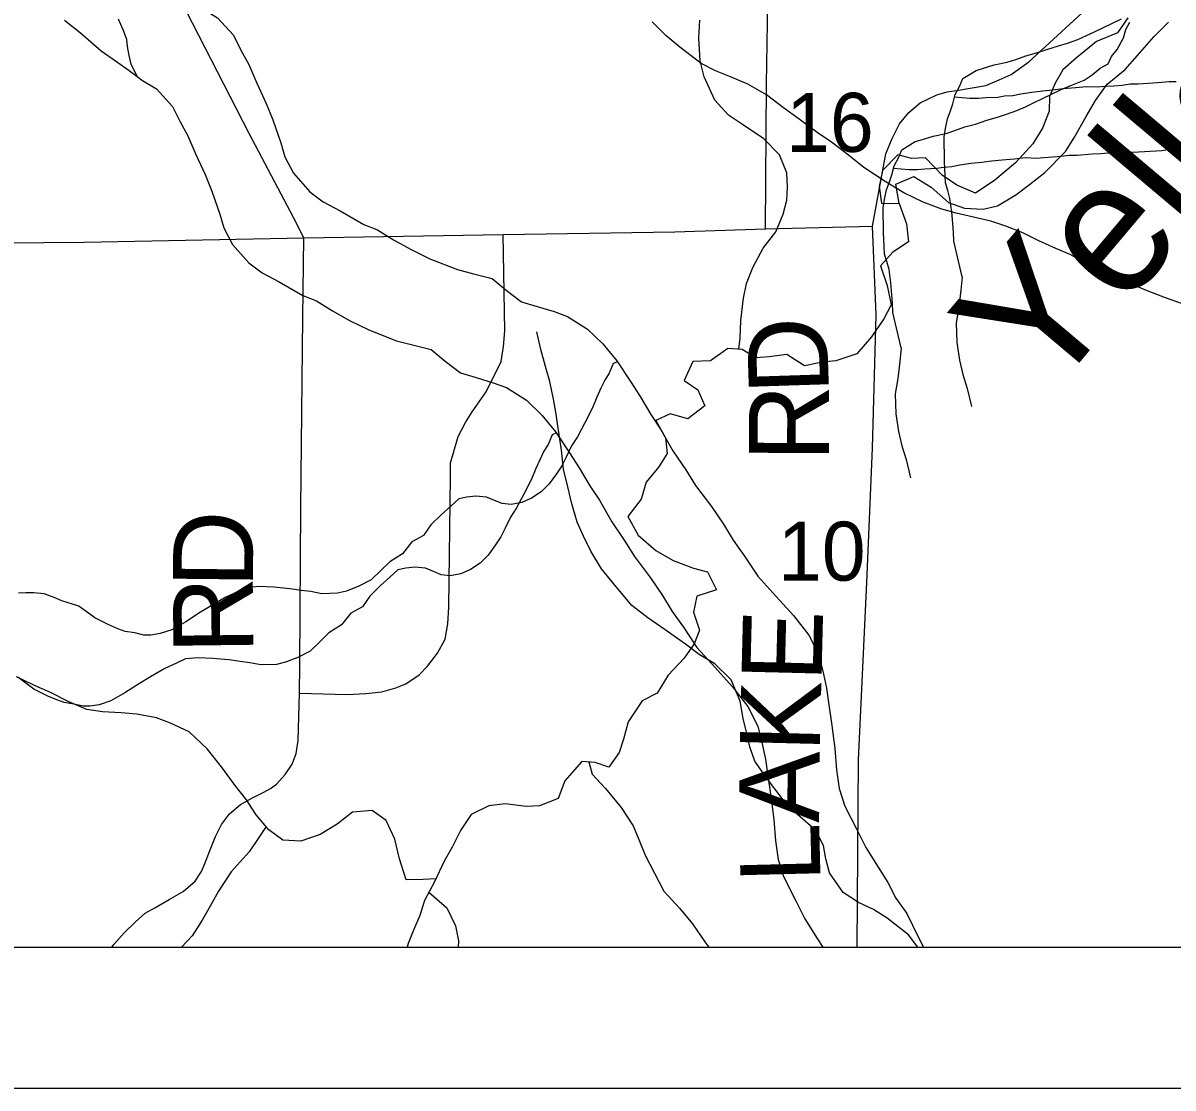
# Model space of a CAD drawing. Extents: x -21.1 to 50.3, y 0 to 22.1.
# Drawn here: x 7.468 to 8.284, y 14 to 14.756 of the extents above; entities that cross this region are included whole.
import ezdxf

# ---------------------------------------------------------------- set-up
doc = ezdxf.new("R2010")
doc.units = 0
for name, color, linetype in [('GM_X_County', 7, 'Continuous'), ('GM_X_County_Road', 7, 'Continuous'), ('GM_X_County_Road_Text', 7, 'Continuous'), ('GM_X_Major_River', 7, 'Continuous'), ('GM_X_Minor_Lake', 7, 'Continuous'), ('GM_X_Minor_River', 7, 'Continuous'), ('GM_X_Minor_River_Text', 7, 'Continuous'), ('GM_X_Section_Text', 7, 'Continuous'), ('GM_X_State_Route', 7, 'Continuous'), ('GM_X_Township_Road', 7, 'Continuous'), ('SH_Cut_Line', 7, 'Continuous'), ('SH_Data', 7, 'Continuous')]:
    doc.layers.add(name, color=color, linetype=linetype)

msp = doc.modelspace()

# ---------------------------------------------------------------- linework, layer by layer
at = {"layer": 'GM_X_County'}
msp.add_lwpolyline([(8.9, 14.74638), (8.9, 20.9), (2.1, 20.9), (2.1, 14.1), (8.89319, 14.1)], dxfattribs=at)
at = {"layer": 'GM_X_County_Road'}
for points in [[(7.6645, 14.30049), (7.66528, 14.41199), (7.66666, 14.54699), (7.66735, 14.60343), (7.66021, 14.61749), (7.62842, 14.67761), (7.57474, 14.78243), (7.56737, 14.79649), (7.56276, 14.80962), (7.56092, 14.82021), (7.56023, 14.83219), (7.56046, 14.84394), (7.56138, 14.90107), (7.56345, 15.14435), (7.56542, 15.20657), (7.56542, 15.2311), (7.5677, 15.5301)], [(8.07096, 14.61173), (8.08041, 14.6631), (8.08502, 14.67393), (8.09009, 14.68452), (8.09677, 14.69259), (8.10483, 14.69927), (8.11658, 14.70503), (8.12395, 14.7071), (8.13063, 14.70802), (8.15136, 14.71171), (8.16104, 14.71563), (8.16933, 14.71954), (8.182, 14.72853), (8.22854, 14.77138)], [(7.66735, 14.60343), (7.8088, 14.60597), (7.93063, 14.60771), (7.9951, 14.60992), (8.07096, 14.61173)], [(8.06009, 14.1), (8.06117, 14.23291), (8.06709, 14.3589), (8.07112, 14.4541), (8.07372, 14.54882), (8.07096, 14.61173)], [(7.22504, 14.59814), (7.51139, 14.60044), (7.66735, 14.60343)], [(7.59993, 14.16665), (7.60469, 14.17863), (7.60884, 14.18715), (7.6146, 14.19452), (7.62243, 14.2012), (7.63049, 14.20581), (7.63902, 14.20996), (7.64362, 14.21272), (7.648, 14.21572), (7.65399, 14.22263), (7.65906, 14.23), (7.66182, 14.23737), (7.66321, 14.24659), (7.66436, 14.28022), (7.6645, 14.30049)], [(7.53115, 14.1), (7.53258, 14.10191), (7.53973, 14.11021), (7.54779, 14.11804), (7.5547, 14.12403), (7.56161, 14.12795), (7.57175, 14.1337), (7.58165, 14.13946), (7.59018, 14.14684), (7.59478, 14.15375), (7.59663, 14.15812), (7.59847, 14.16296), (7.59993, 14.16665)]]:
    msp.add_lwpolyline(points, dxfattribs=at)
at = {"layer": 'GM_X_Major_River'}
for points in [[(7.59609, 14.76577), (7.60601, 14.75977), (7.61749, 14.74734), (7.62251, 14.73676), (7.62828, 14.72655), (7.63408, 14.71332), (7.64064, 14.69895), (7.64529, 14.68723), (7.65111, 14.67095), (7.65384, 14.66111), (7.66001, 14.6494), (7.67149, 14.63621), (7.68104, 14.62907), (7.69323, 14.62272), (7.71, 14.61298), (7.71952, 14.60927), (7.73096, 14.60215), (7.74315, 14.59541), (7.75687, 14.58869), (7.77638, 14.581)], [(7.49744, 14.75807), (7.5089, 14.74905), (7.52342, 14.73627), (7.53372, 14.72914), (7.54326, 14.72238), (7.5528, 14.71525)], [(7.5528, 14.71525), (7.56272, 14.70926), (7.5742, 14.69682), (7.57922, 14.68624), (7.58499, 14.67604), (7.59079, 14.6628), (7.59735, 14.64844), (7.602, 14.63671), (7.60782, 14.62044), (7.61055, 14.6106), (7.61672, 14.59888), (7.6282, 14.58569), (7.63775, 14.57856), (7.64994, 14.5722), (7.66671, 14.56247), (7.67623, 14.55875), (7.68767, 14.55163), (7.69987, 14.5449), (7.71358, 14.53818), (7.73309, 14.53048)], [(7.77638, 14.581), (7.78775, 14.57804), (7.80101, 14.57472), (7.8109, 14.56644), (7.82193, 14.55817), (7.83293, 14.55483), (7.84506, 14.55112), (7.85454, 14.54777), (7.8686, 14.53877), (7.87964, 14.52822), (7.88956, 14.51615), (7.89911, 14.50143), (7.90599, 14.49085), (7.91365, 14.47801), (7.92052, 14.46781), (7.92933, 14.45232), (7.9385, 14.43873), (7.94538, 14.42778), (7.95683, 14.41269), (7.96524, 14.40023), (7.97212, 14.3889), (7.98014, 14.37757), (7.9897, 14.36323), (8.00037, 14.35154), (8.01485, 14.33533), (8.02592, 14.32137), (8.03282, 14.30739), (8.03631, 14.29376), (8.03827, 14.28391), (8.03985, 14.27368), (8.04223, 14.25739), (8.04423, 14.24109), (8.04546, 14.22593), (8.04744, 14.21267), (8.05131, 14.20018), (8.05974, 14.18393), (8.06626, 14.1707), (8.07505, 14.15672), (8.08193, 14.14577), (8.08768, 14.13481), (8.09532, 14.12386), (8.10338, 14.10723), (8.10724, 14.1)], [(7.73309, 14.53048), (7.74446, 14.52753), (7.75773, 14.5242), (7.76762, 14.51592), (7.77864, 14.50765), (7.78964, 14.50432), (7.80177, 14.50061), (7.81125, 14.49726), (7.82531, 14.48825), (7.83635, 14.47771), (7.84627, 14.46564), (7.85583, 14.45091), (7.8627, 14.44034), (7.87036, 14.42749), (7.87724, 14.4173), (7.88604, 14.40181), (7.89521, 14.38822), (7.90209, 14.37726), (7.91354, 14.36217), (7.92195, 14.34971), (7.92883, 14.33838), (7.93685, 14.32706), (7.94641, 14.31271), (7.95708, 14.30102), (7.97156, 14.28482), (7.98263, 14.27086), (7.98953, 14.25687), (7.99302, 14.24324), (7.99498, 14.23339), (7.99656, 14.22316), (7.99894, 14.20687), (8.00094, 14.19057), (8.00217, 14.17541), (8.00415, 14.16215), (8.00802, 14.14966), (8.01645, 14.13341), (8.02297, 14.12018), (8.03176, 14.10621), (8.03566, 14.1)]]:
    msp.add_lwpolyline(points, dxfattribs=at)
at = {"layer": 'GM_X_Minor_Lake'}
for points in [[(8.25235, 14.75979), (8.24486, 14.74908), (8.23012, 14.74286), (8.2158, 14.73133), (8.20601, 14.72288), (8.20078, 14.71333), (8.1967, 14.70379), (8.19641, 14.69353), (8.19158, 14.68133), (8.18485, 14.67025), (8.17245, 14.65683), (8.15776, 14.64453), (8.14418, 14.63529), (8.13085, 14.64086), (8.12054, 14.64799), (8.10867, 14.66041), (8.09881, 14.65994), (8.08892, 14.66251), (8.07801, 14.65139), (8.07584, 14.63997), (8.07746, 14.6282)], [(8.08999, 14.62794), (8.08759, 14.6416), (8.10044, 14.64703), (8.11265, 14.63955), (8.12489, 14.62865), (8.13631, 14.62457), (8.1496, 14.62394), (8.15982, 14.62632), (8.17266, 14.63403), (8.18246, 14.64135), (8.19339, 14.64981), (8.20805, 14.66476), (8.21441, 14.67508), (8.22263, 14.6896), (8.22935, 14.70106), (8.2376, 14.71254), (8.25041, 14.72292), (8.25905, 14.73288), (8.27069, 14.74628), (8.28122, 14.75664)], [(8.07746, 14.6282), (8.08999, 14.62794)]]:
    msp.add_lwpolyline(points, dxfattribs=at)
at = {"layer": 'GM_X_Minor_River'}
for points in [[(7.54914, 14.71799), (7.54484, 14.72691), (7.54328, 14.73298), (7.5421, 14.73943), (7.54169, 14.74437), (7.53899, 14.75119), (7.5359, 14.75877)], [(8.295, 14.55524), (8.2791, 14.56103), (8.26661, 14.56566), (8.25526, 14.57028), (8.24428, 14.57414), (8.23369, 14.57952), (8.22197, 14.58566), (8.21138, 14.5918), (8.20116, 14.59603), (8.18906, 14.60142), (8.17771, 14.60718), (8.1656, 14.61181), (8.155, 14.61529), (8.13037, 14.62113), (8.12015, 14.62385), (8.1069, 14.62886), (8.09328, 14.6354), (8.08005, 14.64344), (8.06494, 14.6534), (8.05399, 14.6622), (8.04191, 14.67137), (8.03171, 14.67827), (8.01887, 14.68783), (8.00792, 14.69587), (7.99584, 14.70505), (7.98261, 14.71272), (7.97012, 14.71772), (7.95952, 14.72196), (7.94931, 14.72734), (7.93421, 14.73881), (7.9244, 14.74722), (7.91459, 14.75676)], [(7.97607, 14.52447), (7.977, 14.53227), (7.97765, 14.54481), (7.9794, 14.56079), (7.98159, 14.57107), (7.98604, 14.58251), (7.9935, 14.59626), (8.00251, 14.60774), (8.00771, 14.62033), (8.01028, 14.63023), (8.01057, 14.63973), (8.0101, 14.64961), (8.00505, 14.66248), (7.99395, 14.67377), (7.97944, 14.68352), (7.96875, 14.69064), (7.95917, 14.70118), (7.95143, 14.71783), (7.94867, 14.7292), (7.94777, 14.74515), (7.94841, 14.75808)], [(8.09144, 14.52534), (8.08556, 14.5506), (8.08514, 14.55705), (8.08473, 14.56313), (8.08392, 14.57148), (8.08273, 14.58097), (8.08117, 14.58666), (8.07962, 14.59197), (8.07921, 14.59729), (8.07877, 14.60716), (8.07867, 14.62501), (8.07978, 14.63186), (8.08089, 14.63756), (8.08314, 14.64327), (8.08463, 14.64822), (8.0865, 14.65469), (8.08952, 14.6604), (8.09177, 14.66611), (8.10125, 14.67186), (8.10657, 14.67341), (8.11417, 14.67573), (8.1233, 14.67768), (8.12937, 14.67961), (8.13659, 14.68231), (8.14419, 14.68425), (8.15217, 14.68696), (8.15977, 14.68928), (8.16623, 14.69122), (8.17345, 14.69391), (8.17952, 14.69661), (8.18522, 14.6993), (8.20458, 14.70852), (8.21179, 14.7116), (8.22129, 14.71545), (8.22698, 14.71928), (8.23266, 14.72387), (8.23835, 14.72694), (8.24061, 14.73227), (8.24477, 14.73724), (8.24929, 14.74562), (8.25078, 14.75132), (8.25379, 14.75666)], [(8.13473, 14.57585), (8.12885, 14.60111), (8.12843, 14.60757), (8.12802, 14.61364), (8.12721, 14.622), (8.12601, 14.63148), (8.12446, 14.63717), (8.12291, 14.64248), (8.1225, 14.6478), (8.12206, 14.65767), (8.12196, 14.67553), (8.12307, 14.68237), (8.12418, 14.68808), (8.12643, 14.69379), (8.12792, 14.69873), (8.12979, 14.7052), (8.1328, 14.71092), (8.13505, 14.71663), (8.14454, 14.72238), (8.14986, 14.72393), (8.15746, 14.72625), (8.16658, 14.7282), (8.17266, 14.73013), (8.17988, 14.73283), (8.18748, 14.73477), (8.19546, 14.73747), (8.20306, 14.7398), (8.20952, 14.74173), (8.21674, 14.74443), (8.22281, 14.74712), (8.22851, 14.74981), (8.24787, 14.75904)], [(8.12932, 14.70358), (8.14008, 14.7026), (8.14617, 14.70263), (8.1515, 14.70304), (8.15987, 14.70347), (8.16481, 14.70426), (8.17052, 14.70467), (8.17622, 14.70584), (8.18421, 14.70702), (8.19182, 14.70783), (8.19867, 14.70862), (8.20628, 14.70942), (8.21503, 14.71023), (8.22301, 14.71104), (8.23063, 14.7107), (8.23595, 14.71111), (8.24242, 14.71152), (8.24813, 14.71194), (8.25384, 14.71273), (8.25954, 14.71276), (8.2702, 14.71358), (8.27629, 14.71399), (8.28161, 14.7144), (8.28656, 14.71443)], [(8.08603, 14.65306), (8.09679, 14.65208), (8.10288, 14.65212), (8.10821, 14.65253), (8.11658, 14.65295), (8.12152, 14.65374), (8.12723, 14.65415), (8.13293, 14.65532), (8.14092, 14.65651), (8.14853, 14.65731), (8.15538, 14.65811), (8.16299, 14.65891), (8.17174, 14.65972), (8.17973, 14.66052), (8.18734, 14.66018), (8.19267, 14.66059), (8.19913, 14.66101), (8.20484, 14.66142), (8.21055, 14.66221), (8.21626, 14.66224), (8.22691, 14.66306), (8.233, 14.66347), (8.23832, 14.66388), (8.24327, 14.66391), (8.24974, 14.66433), (8.25583, 14.66436), (8.27638, 14.66561), (8.28627, 14.66719)], [(8.08999, 14.62794), (8.09505, 14.61355), (8.09668, 14.60064), (8.08536, 14.59332), (8.07672, 14.58374), (8.0814, 14.56973), (8.08418, 14.55607), (8.07896, 14.54614), (8.07035, 14.53314), (8.05982, 14.52127), (8.04507, 14.51619), (8.03559, 14.51534), (8.02272, 14.51256), (8.01012, 14.5208), (7.99761, 14.51916), (7.98813, 14.51832), (7.97859, 14.5243), (7.96834, 14.52497), (7.9559, 14.51611), (7.94338, 14.51562), (7.93743, 14.50226), (7.94697, 14.49551), (7.95201, 14.48416), (7.93995, 14.47493), (7.92739, 14.47861), (7.91719, 14.47395), (7.92413, 14.46148), (7.92537, 14.45047), (7.91938, 14.44092), (7.91037, 14.43019), (7.90669, 14.418), (7.89731, 14.40575), (7.90464, 14.39253), (7.91726, 14.38162), (7.92947, 14.37452), (7.94393, 14.36896), (7.95382, 14.36639), (7.96039, 14.35353), (7.94639, 14.34922), (7.94384, 14.3378), (7.94813, 14.32492), (7.94442, 14.31539), (7.9373, 14.30506), (7.92602, 14.29317), (7.91817, 14.28018), (7.90759, 14.27476), (7.89748, 14.25985), (7.89417, 14.24766), (7.89122, 14.23813), (7.88373, 14.2278), (7.87421, 14.23114), (7.86472, 14.23181), (7.8527, 14.21801), (7.84788, 14.20543), (7.83464, 14.20037), (7.82516, 14.1999), (7.81035, 14.20166), (7.79859, 14.20041), (7.78613, 14.19421), (7.77864, 14.18274), (7.77267, 14.17091), (7.76707, 14.16097), (7.75999, 14.14647), (7.7529, 14.13311), (7.74958, 14.12243), (7.74512, 14.11214), (7.74141, 14.1026), (7.74063, 14.1)], [(8.13473, 14.57585), (8.13366, 14.56636), (8.13222, 14.55422), (8.1304, 14.5432), (8.13087, 14.52917), (8.13285, 14.51667), (8.13518, 14.50645), (8.13828, 14.49661), (8.14139, 14.48373)], [(8.10313, 14.1), (8.09663, 14.10879), (8.08152, 14.12065), (8.0717, 14.12678), (8.06111, 14.13177), (8.05015, 14.13867), (8.04038, 14.15277), (8.03779, 14.16265), (8.03633, 14.17214), (8.03071, 14.1828), (8.01788, 14.19426), (8.00771, 14.20456), (7.99567, 14.22019), (7.9874, 14.23201), (7.98405, 14.24227), (7.98146, 14.25253), (7.97925, 14.2624), (7.97705, 14.27456), (7.9707, 14.28977), (7.95902, 14.30123), (7.94805, 14.30774), (7.93824, 14.31501), (7.92389, 14.32535), (7.91142, 14.33377), (7.90009, 14.34256), (7.88918, 14.35553), (7.87864, 14.36849), (7.87113, 14.38106), (7.86589, 14.39172), (7.8614, 14.40161), (7.85732, 14.41567), (7.85474, 14.42669), (7.85178, 14.43922), (7.85036, 14.45289), (7.8478, 14.46846), (7.84635, 14.47833), (7.84452, 14.48897), (7.84195, 14.5015), (7.83898, 14.51215), (7.83565, 14.52431), (7.8327, 14.53684)], [(8.09144, 14.52534), (8.09037, 14.51585), (8.08893, 14.5037), (8.08711, 14.49269), (8.08758, 14.47866), (8.08956, 14.46616), (8.0919, 14.45593), (8.09499, 14.44609), (8.0981, 14.43322)], [(7.88994, 14.51555), (7.88701, 14.51427), (7.88397, 14.50743), (7.88093, 14.5025), (7.87827, 14.49681), (7.87523, 14.49036), (7.87219, 14.48277), (7.86687, 14.47214), (7.86155, 14.46227), (7.85738, 14.45582), (7.85358, 14.44785), (7.85054, 14.44178), (7.84674, 14.43609), (7.84143, 14.42888), (7.83573, 14.42319), (7.8289, 14.41865), (7.82207, 14.41562), (7.81449, 14.41411), (7.80804, 14.41488), (7.80273, 14.41717), (7.79705, 14.41946), (7.78946, 14.42023), (7.78301, 14.41948), (7.77733, 14.41835), (7.77163, 14.41304), (7.7648, 14.40697), (7.75759, 14.39977), (7.75227, 14.39218), (7.74393, 14.38764), (7.73747, 14.37929), (7.72836, 14.37361), (7.72229, 14.36754), (7.71508, 14.36072), (7.70636, 14.35617), (7.69763, 14.35277), (7.69118, 14.35126), (7.68018, 14.3509), (7.67222, 14.35243), (7.6654, 14.3532), (7.65743, 14.35435), (7.64606, 14.35551), (7.63544, 14.35591), (7.62672, 14.35516), (7.62027, 14.35213), (7.61192, 14.34835), (7.60168, 14.34229), (7.59409, 14.33774), (7.58347, 14.33092), (7.5736, 14.32524), (7.56525, 14.3226), (7.5588, 14.32147), (7.55388, 14.32148), (7.54743, 14.32301), (7.54061, 14.32416), (7.5353, 14.32606), (7.52885, 14.32873), (7.519, 14.33369), (7.50763, 14.34206), (7.4955, 14.34588), (7.49019, 14.34817), (7.48299, 14.35084), (7.47579, 14.35161), (7.4701, 14.35162), (7.46479, 14.35124)], [(7.84666, 14.46504), (7.84372, 14.46375), (7.84068, 14.45692), (7.83764, 14.45198), (7.83499, 14.44629), (7.83194, 14.43984), (7.8289, 14.43225), (7.82359, 14.42162), (7.81827, 14.41176), (7.81409, 14.40531), (7.81029, 14.39734), (7.80725, 14.39126), (7.80345, 14.38557), (7.79814, 14.37836), (7.79244, 14.37268), (7.78561, 14.36813), (7.77878, 14.3651), (7.7712, 14.3636), (7.76475, 14.36437), (7.75944, 14.36665), (7.75376, 14.36894), (7.74617, 14.36971), (7.73973, 14.36896), (7.73404, 14.36783), (7.72835, 14.36252), (7.72151, 14.35646), (7.7143, 14.34925), (7.70899, 14.34167), (7.70064, 14.33712), (7.69418, 14.32878), (7.68508, 14.32309), (7.679, 14.31703), (7.67179, 14.3102), (7.66307, 14.30566), (7.65434, 14.30225), (7.64789, 14.30074), (7.63689, 14.30038), (7.62893, 14.30191), (7.62211, 14.30268), (7.61414, 14.30384), (7.60277, 14.305), (7.59215, 14.30539), (7.58343, 14.30465), (7.57698, 14.30162), (7.56863, 14.29783), (7.55839, 14.29177), (7.5508, 14.28723), (7.54018, 14.28041), (7.53031, 14.27473), (7.52196, 14.27208), (7.51552, 14.27095), (7.51059, 14.27096), (7.50414, 14.27249), (7.49732, 14.27364), (7.49201, 14.27555), (7.48556, 14.27822), (7.47571, 14.28317), (7.46434, 14.29154)], [(7.76096, 14.14846), (7.75201, 14.14792), (7.73987, 14.1478), (7.73518, 14.16258), (7.73202, 14.1766), (7.72583, 14.18985), (7.7159, 14.19697), (7.70187, 14.1957), (7.69094, 14.18724), (7.67886, 14.17991), (7.66525, 14.17522), (7.65234, 14.17586), (7.6424, 14.18336), (7.63358, 14.19392), (7.62665, 14.20449), (7.6186, 14.21467), (7.60899, 14.22789), (7.59863, 14.24071), (7.586, 14.25275), (7.57266, 14.25908), (7.56276, 14.26279), (7.5487, 14.26531), (7.53768, 14.26635), (7.52439, 14.26699), (7.51337, 14.26878), (7.50004, 14.27435), (7.48746, 14.2807), (7.47565, 14.28591), (7.46346, 14.29187)], [(7.86955, 14.23146), (7.87201, 14.22275), (7.88159, 14.21259), (7.89271, 14.19901), (7.90118, 14.18617), (7.90506, 14.17633), (7.90971, 14.16535), (7.92285, 14.13964), (7.93396, 14.12759), (7.94316, 14.11665), (7.95201, 14.10382), (7.95477, 14.1)], [(7.64053, 14.1856), (7.63487, 14.17721), (7.6285, 14.16765), (7.61573, 14.15348), (7.60675, 14.13971), (7.60077, 14.12902), (7.59517, 14.11908), (7.58806, 14.108), (7.58047, 14.1)], [(7.7561, 14.13913), (7.76889, 14.12794), (7.77507, 14.11508), (7.77707, 14.10446), (7.77697, 14.1)]]:
    msp.add_lwpolyline(points, dxfattribs=at)
at = {"layer": 'GM_X_State_Route'}
msp.add_lwpolyline([(6.5142, 14.9441), (6.51283, 14.60317), (6.513, 14.41466), (6.51114, 14.29418), (6.5113, 14.24348), (6.50995, 14.1), (8.9, 14.1), (8.9, 17.84218)], dxfattribs=at)
at = {"layer": 'GM_X_Township_Road'}
for points in [[(7.9951, 14.60992), (7.99581, 14.71247), (7.99755, 14.82999), (7.99792, 14.84814)], [(7.66436, 14.28022), (7.69822, 14.2793), (7.71135, 14.27999), (7.72264, 14.28114), (7.73255, 14.28414), (7.73969, 14.2869), (7.74913, 14.29335), (7.75512, 14.29934), (7.76227, 14.30879), (7.76756, 14.31869), (7.76964, 14.32952), (7.77033, 14.34127), (7.77148, 14.43411), (7.77148, 14.44379), (7.77332, 14.45024), (7.77701, 14.46245), (7.78208, 14.47235), (7.78692, 14.47995), (7.79682, 14.49424), (7.80742, 14.51566), (7.80903, 14.52649), (7.80995, 14.53755), (7.8088, 14.60597)]]:
    msp.add_lwpolyline(points, dxfattribs=at)
at = {"layer": 'SH_Cut_Line'}
msp.add_lwpolyline([(6.50995, 14.1), (8.9, 14.1), (8.9, 20.9), (6.52955, 20.9), (6.52977, 20.39859), (6.52273, 19.34666), (6.52255, 18.97782), (6.52225, 18.35692), (6.52196, 17.81036), (6.52053, 17.72081), (6.52013, 17.69645), (6.52222, 16.85672), (6.52315, 16.46813), (6.52123, 16.24517), (6.51982, 16.08256), (6.51595, 15.49226), (6.51465, 15.30312), (6.514, 15.09364), (6.51464, 15.03489), (6.5142, 14.9441), (6.51283, 14.60317), (6.513, 14.41466), (6.51114, 14.29418), (6.5113, 14.24348)], close=True, dxfattribs=at)
at = {"layer": 'SH_Data'}
msp.add_line((2, 14), (9, 14), dxfattribs=at)

# ---------------------------------------------------------------- texts
at = {"layer": 'GM_X_County_Road_Text'}
for s, rotation, p in [('D', 91.85616, (8.04018, 14.49338)), ('R', 89.76582, (8.04002, 14.44449)), ('D', 89.40257, (7.63114, 14.35473)), ('R', 90.67134, (7.63168, 14.3084)), ('E', 88.56843, (8.03472, 14.28796)), ('K', 88.60104, (8.0335, 14.23798)), ('A', 89.53371, (8.0331, 14.18823)), ('L', 91.46156, (8.03418, 14.14625))]:
    msp.add_text(s, height=0.05682, rotation=rotation, dxfattribs=at).set_placement(p)
at = {"layer": 'GM_X_Minor_River_Text'}
msp.add_text('Yellow', height=0.094746, rotation=49.8757, dxfattribs=at).set_placement((8.19439, 14.48702))
at = {"layer": 'GM_X_Section_Text'}
for s, p in [('16', (8.00961, 14.66457)), ('10', (8.00386, 14.36016))]:
    msp.add_text(s, height=0.041856, rotation=0.00001, dxfattribs=at).set_placement(p)

doc.saveas('drawing.dxf')
